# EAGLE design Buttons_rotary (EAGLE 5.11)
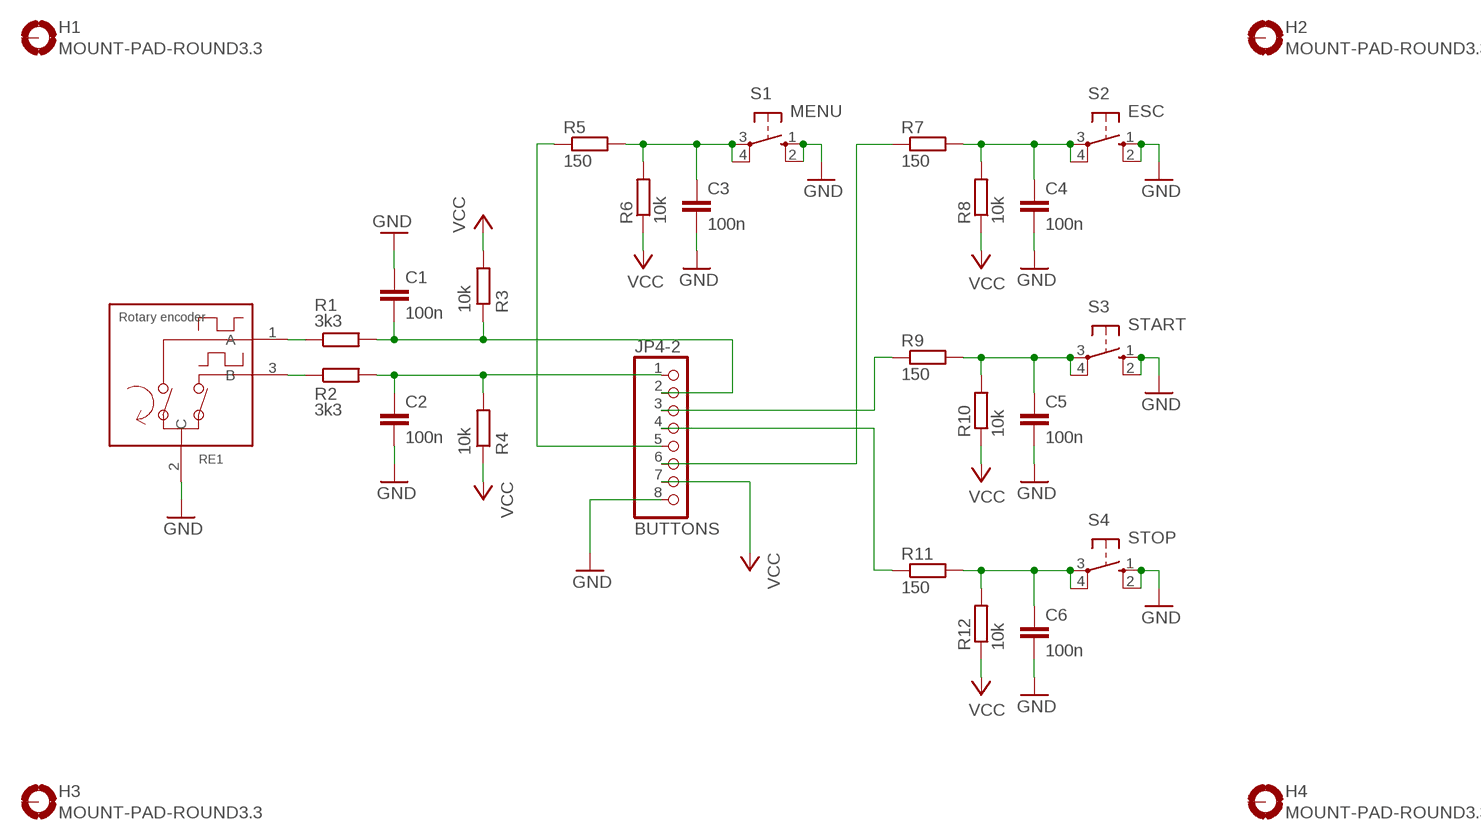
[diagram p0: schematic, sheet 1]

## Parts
C1  100n  C-EU025-030X050  [C025-030X050]
C2  100n  C-EU025-030X050  [C025-030X050]
C3  100n  C-EU025-030X050  [C025-030X050]
C4  100n  C-EU025-030X050  [C025-030X050]
C5  100n  C-EU025-030X050  [C025-030X050]
C6  100n  C-EU025-030X050  [C025-030X050]
H1  MOUNT-PAD-ROUND3.3  [3,3-PAD]
H2  MOUNT-PAD-ROUND3.3  [3,3-PAD]
H3  MOUNT-PAD-ROUND3.3  [3,3-PAD]
H4  MOUNT-PAD-ROUND3.3  [3,3-PAD]
JP4-2  BUTTONS  PINHD-1X8  [1X08]
R1  3k3  R-EU_0207/7  [0207/7]
R2  3k3  R-EU_0207/7  [0207/7]
R3  10k  R-EU_0207/7  [0207/7]
R4  10k  R-EU_0207/7  [0207/7]
R5  150  R-EU_0207/7  [0207/7]
R6  10k  R-EU_0207/7  [0207/7]
R7  150  R-EU_0207/7  [0207/7]
R8  10k  R-EU_0207/7  [0207/7]
R9  150  R-EU_0207/7  [0207/7]
R10  10k  R-EU_0207/7  [0207/7]
R11  150  R-EU_0207/7  [0207/7]
R12  10k  R-EU_0207/7  [0207/7]
RE1  Rotary encoder  RE24  [RE24]
S1  MENU  P-B1729  [P-B1729]
S2  ESC  P-B1729  [P-B1729]
S3  START  P-B1729  [P-B1729]
S4  STOP  P-B1729  [P-B1729]

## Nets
GND: C1.1 C2.2 C3.2 C4.2 C5.2 C6.2 JP4-2.8 RE1.2(C) S1.1(S) S1.2(S1) S2.1(S) S2.2(S1) S3.1(S) S3.2(S1) S4.1(S) S4.2(S1)
N$1: C3.1 R5.2 R6.2 S1.3(P) S1.4(P1)
N$2: JP4-2.5 R5.1
N$3: R1.1 RE1.1(A)
N$4: R2.1 RE1.3(B)
N$5: C2.1 JP4-2.1 R2.2 R4.2
N$6: C1.2 JP4-2.2 R1.2 R3.1
N$7: C4.1 R7.2 R8.2 S2.3(P) S2.4(P1)
N$8: C5.1 R9.2 R10.2 S3.3(P) S3.4(P1)
N$9: JP4-2.3 R9.1
N$10: C6.1 R11.2 R12.2 S4.3(P) S4.4(P1)
N$11: JP4-2.6 R7.1
N$12: JP4-2.4 R11.1
VCC: JP4-2.7 R3.2 R4.1 R6.1 R8.1 R10.1 R12.1
Unconnected: H1.B3,3(MOUNT) H2.B3,3(MOUNT) H3.B3,3(MOUNT) H4.B3,3(MOUNT)

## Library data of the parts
C1-C6 = rcl:C-EU: CAPACITOR, European symbol
H1-H4 = holes:MOUNT-PAD-ROUND: MOUNTING PAD, round
JP4-2 = pinhead:PINHD-1X8: PIN HEADER
R1-R12 = rcl:R-EU_: RESISTOR, European symbol
RE1 = rotary-encoder:RE24
S1-S4 = switch-omron:P-B1729

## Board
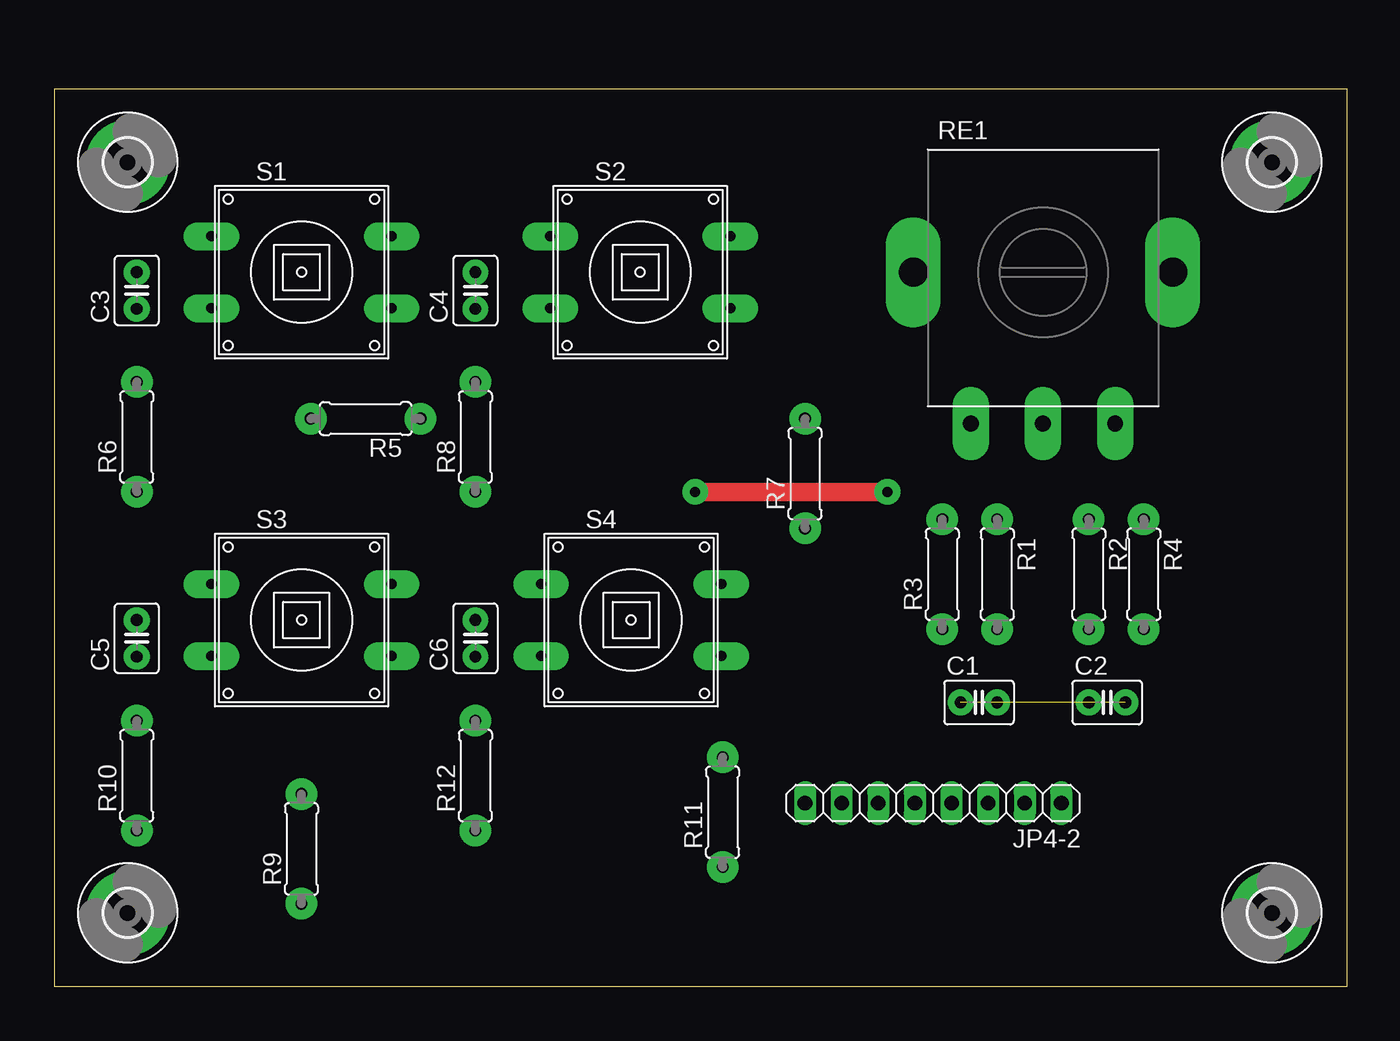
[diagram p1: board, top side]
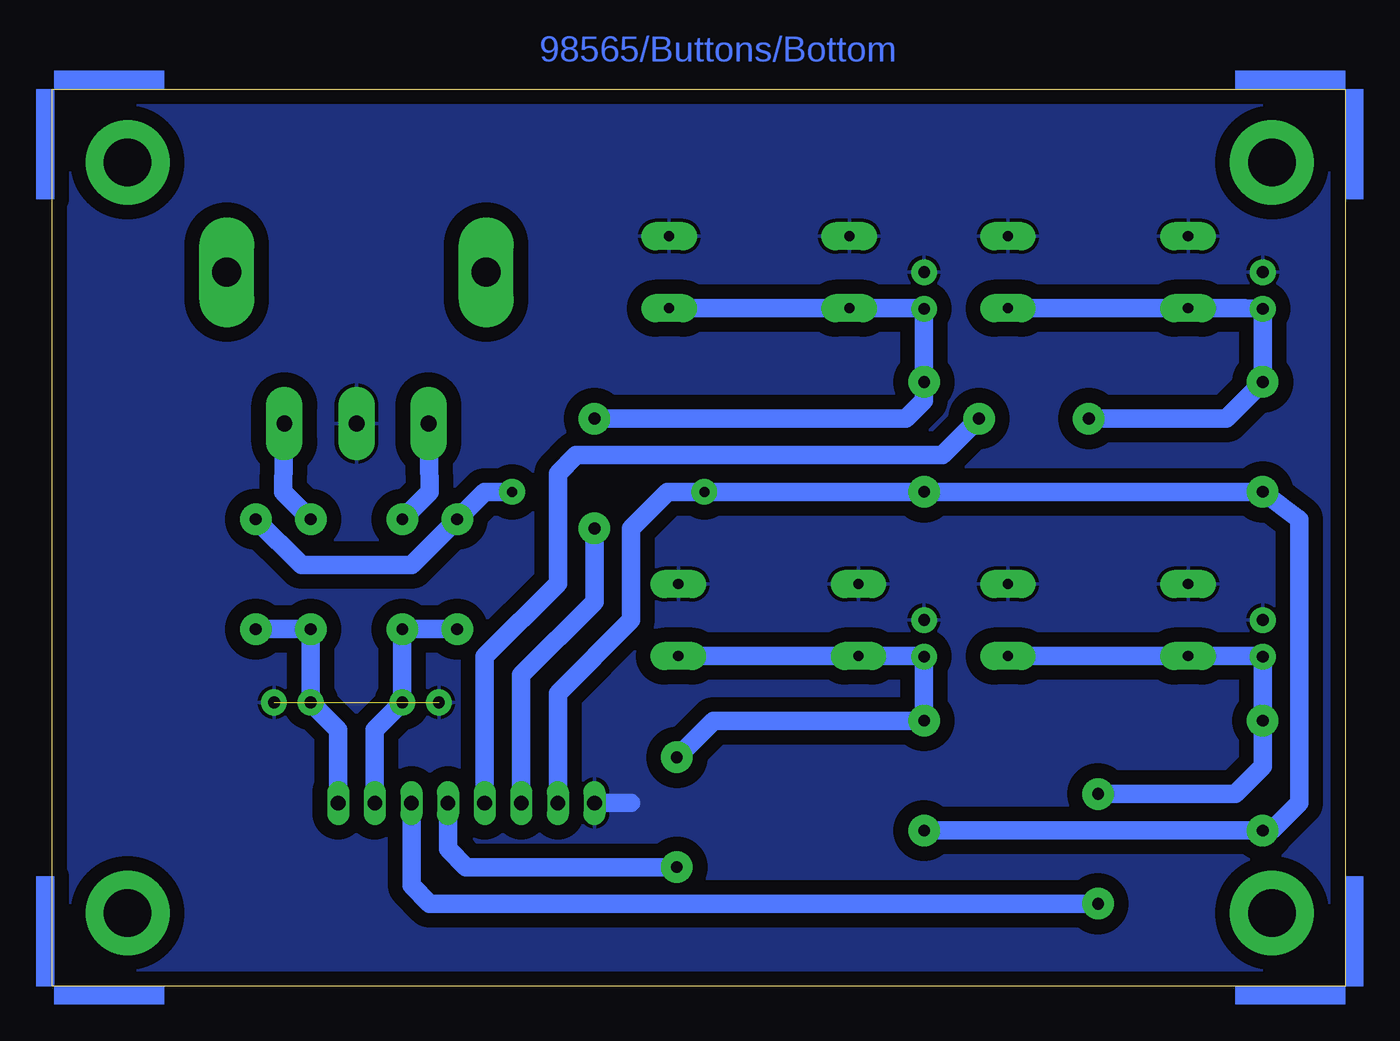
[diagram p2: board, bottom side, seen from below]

Size 89.69 x 62.22 mm. Coordinates in mm from the lower left corner, seen from the top.
Outline: 0,0 89.69,0 89.69,62.22 0,62.22 0,0
Copper layers (1*16): Top 0.035mm / dielectric 1.5mm / Bottom 0.035mm
Design rules "default *": minimum track width 10mil, minimum drill 24mil, track to track 12mil, track to pad 12mil, pad to pad 12mil, via to via 12mil, smd to smd 8mil, copper to edge 40mil, drill to drill 8mil, minimum pad ring 10mil, minimum via ring 8mil, stop-mask expansion 4mil, vias tented up to drill 0mil, thermal gap 10mil

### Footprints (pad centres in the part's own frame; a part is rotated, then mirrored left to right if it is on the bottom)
C025-030X050 = drill 0.813 pad 1.778 round: 1 -1.27,0; 2 1.27,0
3,3-PAD = drill 3.3 pad 5.842 round: B3,3 0,0
1X08 = drill 1.016 long: 1 -8.89,0; 2 -6.35,0; 3 -3.81,0; 4 -1.27,0; 5 1.27,0; 6 3.81,0; 7 6.35,0; 8 8.89,0
0207/7 = drill 0.813 pad 2.184 round: 1 -3.81,0; 2 3.81,0
RE24 = drill 1.1 pad 2.54 long: 1 -5,-10.5; 2 0,-10.5; 3 5,-10.5 | drill 2 pad 3.81 long: M1 -9,0; M2 9,0
P-B1729 = drill 0.7 pad 1.93 long: 1 -6.25,2.5; 2 6.25,2.5; 3 -6.25,-2.5; 4 6.25,-2.5

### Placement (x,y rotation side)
C1  64.14,19.68 0 top
C2  73.03,19.68 0 top
C3  5.71,48.26 90 top
C4  29.21,48.26 90 top
C5  5.71,24.13 90 top
C6  29.21,24.13 90 top
H1  84.45,57.15 0 top
H2  5.08,57.15 0 top
H3  5.08,5.08 0 top
H4  84.45,5.08 0 top
JP4-2  60.96,12.7 180 top
R1  65.41,28.57 270 top
R2  71.75,28.57 270 top
R3  61.59,28.57 90 top
R4  75.56,28.57 270 top
R5  21.59,39.37 180 top
R6  5.71,38.1 90 top
R7  52.07,35.56 90 top
R8  29.21,38.1 90 top
R9  17.14,9.53 90 top
R10  5.71,14.61 90 top
R11  46.35,12.06 90 top
R12  29.21,14.61 90 top
RE1  68.58,49.53 0 top
S1  17.14,49.53 0 top
S2  40.64,49.53 0 top
S3  17.14,25.4 0 top
S4  40.01,25.4 0 top
U$5  [ANGLE-ARROW-NW1]  0,62.23 0 top
U$6  [ANGLE-ARROW-NW1]  89.53,62.23 270 top
U$7  [ANGLE-ARROW-NW1]  89.53,0 180 top
U$8  [ANGLE-ARROW-NW1]  0,0 90 top

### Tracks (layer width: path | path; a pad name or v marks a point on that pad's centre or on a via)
GND  (1 unrouted)
  Bottom 1.27: 49.53,12.7 JP4-2.8
  pour Bottom (isolate 1.016): 0,62.23 89.53,62.23 89.53,0 0,0
N$1
  Bottom 1.27: R5.2 8.26,39.37 R6.2 C3.1 6.99,47.03 S1.3 S1.4
N$2
  Bottom 1.27: R5.1 27.94,36.83 53.34,36.83 54.61,35.56 54.61,27.94 59.69,22.86 JP4-2.5
N$3
  Bottom 1.27: R1.1 63.5,34.29 RE1.1
N$4
  Bottom 1.27: R2.1 73.66,34.29 RE1.3
N$5
  Bottom 1.27: R4.2 R2.2 C2.1 69.85,17.78 JP4-2.1
N$6
  Bottom 1.27: JP4-2.2 67.31,17.78 C1.2 R1.2 R3.1
N$7
  Bottom 1.27: R7.2 30.48,39.37 29.21,40.64 R8.2 C4.1 29.21,47.03 S2.3 S2.4
N$8
  Bottom 1.27: R9.2 7.62,13.34 5.71,15.24 R10.2 C5.1 5.71,22.9 S3.3 S3.4
N$9
  Bottom 1.27: R9.1 63.5,5.71 64.77,6.99 JP4-2.3
N$10
  Bottom 1.27: R11.2 43.81,18.41 R12.2 C6.1 29.21,22.9 S4.3 S4.4
N$11
  Bottom 1.27: JP4-2.6 57.15,21.59 52.07,26.67 R7.1
N$12
  Bottom 1.27: R11.1 60.96,8.26 62.23,9.53 JP4-2.4
VCC  (via drill 0.7 pad 1.78)
  Top 1.27: v44.45,34.29 v57.78,34.29
  Bottom 1.27: R12.1 R10.1 5.08,10.79 3.17,12.7 3.17,32.38 R6.1 R8.1 v44.45,34.29 46.99,34.29 49.53,31.75 49.53,25.4 54.61,20.32 JP4-2.7 | R4.1 72.39,29.21 64.77,29.21 R3.2 59.69,34.29 v57.78,34.29

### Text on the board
Bottom: 98565/Buttons/Bottom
